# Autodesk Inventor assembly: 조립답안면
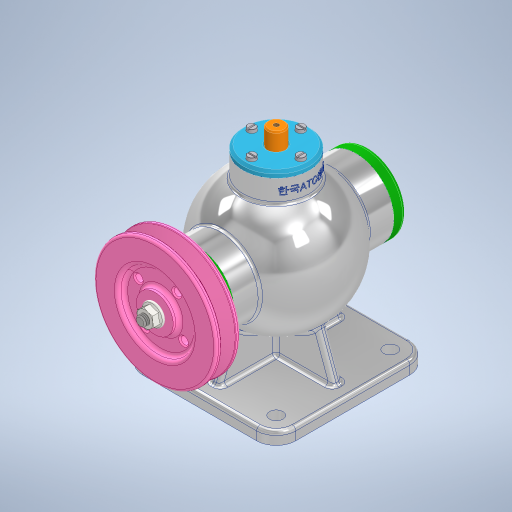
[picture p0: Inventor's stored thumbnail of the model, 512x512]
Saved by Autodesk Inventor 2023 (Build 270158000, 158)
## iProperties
Created: 2023-07
Part Number: 조립답안면
Document SubType Name: Assembly
Designer: Owner
Author: Owner
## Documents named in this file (16)
- C:\Users\Owner\Desktop\730711V1007\조립답안면.iam
- C:\Users\Owner\Desktop\730711V1007\본체.ipt
- C:\Users\Owner\Desktop\730711V1007\뒤커버.ipt
- C:\Users\Owner\Desktop\730711V1007\상부커버.ipt
- C:\Users\Owner\Desktop\730711V1007\앞커버.ipt
- C:\Users\Owner\Desktop\730711V1007\베어링- 6202.ipt
- KS B 2023 - 6202 - 15 x 35 x 11 - 7.8.ipt
- C:\Users\Owner\Desktop\730711V1007\칼라.ipt
- C:\Users\Owner\Desktop\730711V1007\편심축.ipt
- C:\Users\Owner\Desktop\730711V1007\V-벨트풀리.ipt
- C:\Users\Owner\Desktop\730711V1007\오일실 15 30 7.ipt
- C:\Users\Owner\Desktop\730711V1007\키 4 x 4 x 12.ipt
- C:\Users\Owner\Desktop\730711V1007\너트 M8.ipt
- C:\Users\Owner\Desktop\730711V1007\볼트 M4 x 16.ipt
- C:\Users\Owner\Desktop\730711V1007\볼트 M4 x 12.ipt
- C:\Users\Owner\Desktop\730711V1007\슬라이드.ipt
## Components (15 placed, 4 different names)
1. KS B 2023 - 6202 - 15 x 35 x 11 - 7.8:1
2. KS B 2023 - 6202 - 15 x 35 x 11 - 7.8:2
3. V-벨트풀리:1
4. ISO 4762 M4 x 16:1
5. ISO 4762 M4 x 16:2
6. ISO 4762 M4 x 16:3
7. ISO 4762 M4 x 16:4
8. ISO 4762 M4 x 16:5
9. ISO 4762 M4 x 16:6
10. ISO 4762 M4 x 16:7
11. ISO 4762 M4 x 16:8
12. KS B 1021 - 에 따름 ISO 1207 - 미터 A  M 4 x 12:1
13. KS B 1021 - 에 따름 ISO 1207 - 미터 A  M 4 x 12:2
14. KS B 1021 - 에 따름 ISO 1207 - 미터 A  M 4 x 12:3
15. KS B 1021 - 에 따름 ISO 1207 - 미터 A  M 4 x 12:4
